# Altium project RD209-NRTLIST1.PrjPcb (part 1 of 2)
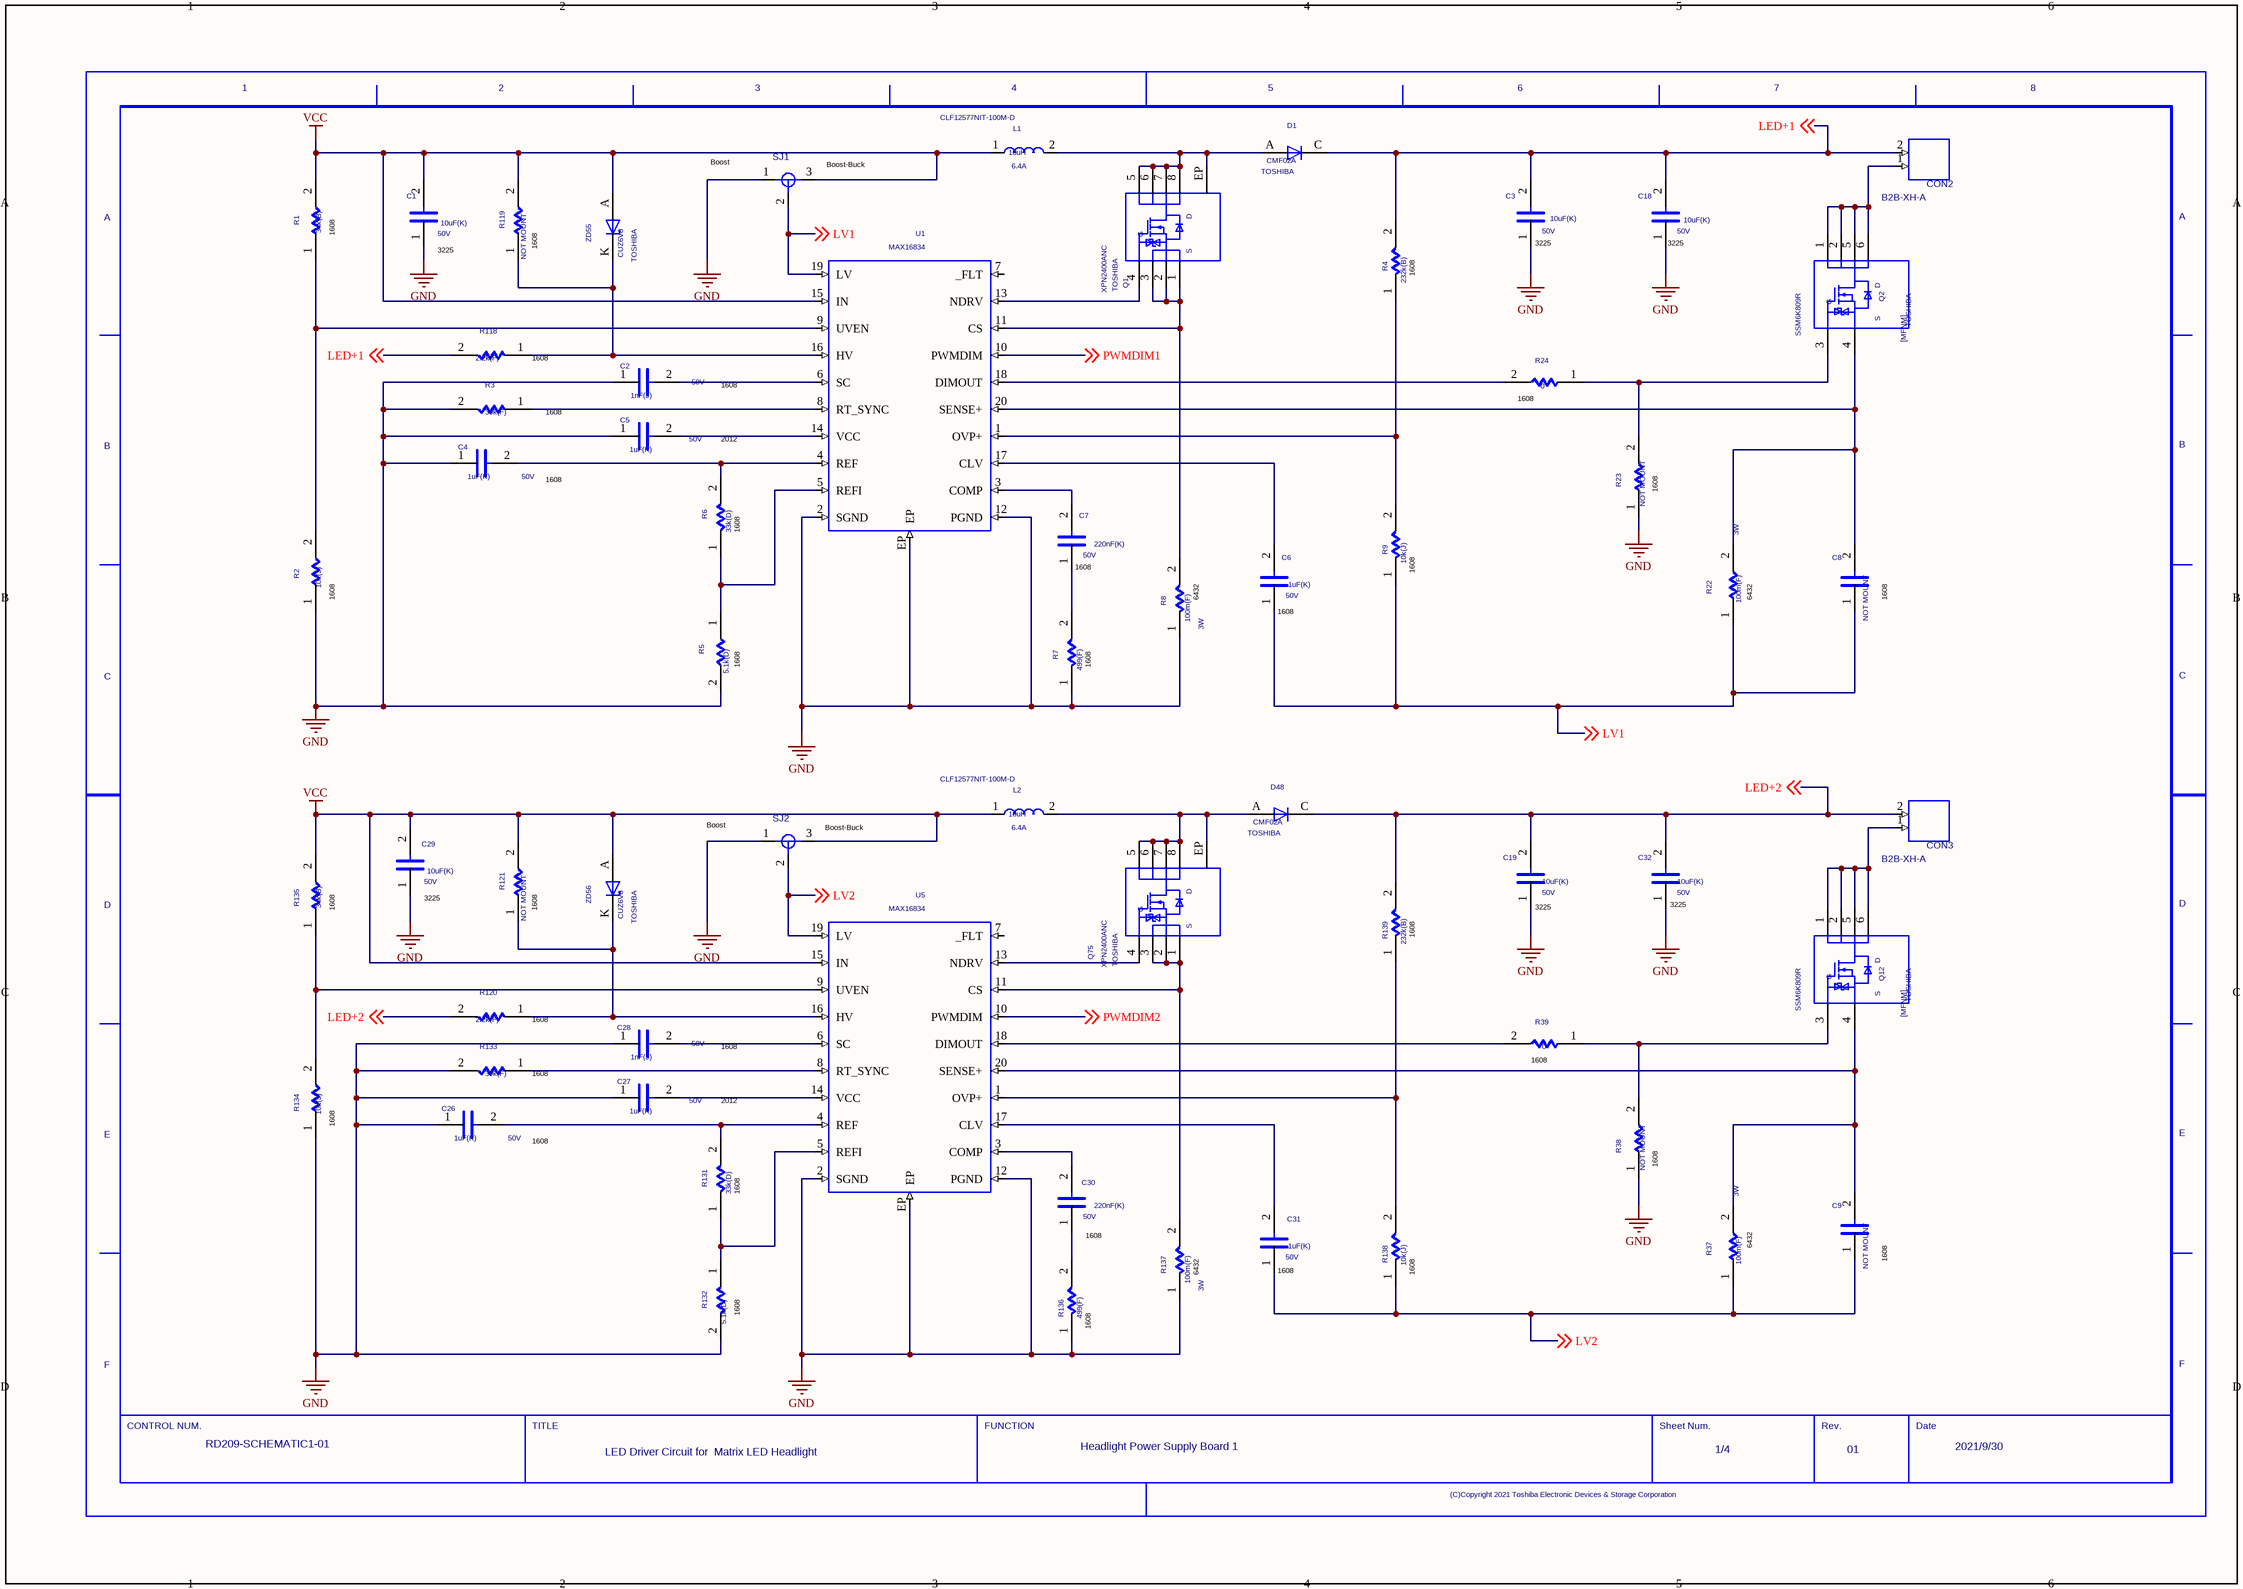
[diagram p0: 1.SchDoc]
4 sheets, 250 parts. Net scope: global (net labels, ports and power ports of the same name join across sheets).
Sheets:
  1.SchDoc
  2.SchDoc
  3.SchDoc
  4.SchDoc

## Sheet 1.SchDoc
size 420 x 297 mm

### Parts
(Parts that share a designator on the sheet are numbered #1, #2 ... from top to bottom, then left to right.)
C1  VAL2: 50V  VAL1: 10uF(K)  (hidden comment: C)
C2  VAL2: 50V  VAL1: 1nF(J)  (hidden comment: C)
C3  VAL2: 50V  VAL1: 10uF(K)  (hidden comment: C)
C4  VAL2: 50V  VAL1: 1uF(K)  (hidden comment: C)
C5  VAL2: 50V  VAL1: 1uF(K)  (hidden comment: C)
C6  VAL2: 50V  VAL1: 1uF(K)  (hidden comment: C)
C7  VAL2: 50V  VAL1: 220nF(K)  (hidden comment: C)
C8  NOTMOUNT: NOT MOUNT  (hidden comment: C)
C9  NOTMOUNT: NOT MOUNT  (hidden comment: C)
C18  VAL2: 50V  VAL1: 10uF(K)  (hidden comment: C)
C19  VAL2: 50V  VAL1: 10uF(K)  (hidden comment: C)
C26  VAL2: 50V  VAL1: 1uF(K)  (hidden comment: C)
C27  VAL2: 50V  VAL1: 1uF(K)  (hidden comment: C)
C28  VAL2: 50V  VAL1: 1nF(J)  (hidden comment: C)
C29  VAL2: 50V  VAL1: 10uF(K)  (hidden comment: C)
C30  VAL2: 50V  VAL1: 220nF(K)  (hidden comment: C)
C31  VAL2: 50V  VAL1: 1uF(K)  (hidden comment: C)
C32  VAL2: 50V  VAL1: 10uF(K)  (hidden comment: C)
CON2  B2B-XH-A  [B2B-XH-A]
CON3  B2B-XH-A  [B2B-XH-A]
D1  USERCOMPTEXT3: TOSHIBA  VAL3: CMF02A  (hidden comment: D)
D48  USERCOMPTEXT3: TOSHIBA  VAL3: CMF02A  (hidden comment: D)
L1  VAL3: CLF12577NIT-100M-D  VAL2: 6.4A  VAL1: 10uH  (hidden comment: L)
L2  VAL3: CLF12577NIT-100M-D  VAL2: 6.4A  VAL1: 10uH  (hidden comment: L)
Q1  USERCOMPTEXT3: TOSHIBA  VAL3: XPN2400ANC  (hidden comment: MFNKR1)
Q2  USERCOMPTEXT3: TOSHIBA  VAL3: SSM6K809R  (hidden comment: MFNM)
Q12  USERCOMPTEXT3: TOSHIBA  VAL3: SSM6K809R  (hidden comment: MFNM)
Q75  USERCOMPTEXT3: TOSHIBA  VAL3: XPN2400ANC  (hidden comment: MFNKR1)
R1  VAL1: 34k(B)  (hidden comment: R)
R2  VAL1: 10k(J)  (hidden comment: R)
R3  VAL1: 39k(F)  (hidden comment: R)
R4  VAL1: 232k(B)  (hidden comment: R)
R5  VAL1: 5.1k(D)  (hidden comment: R)
R6  VAL1: 33k(D)  (hidden comment: R)
R7  VAL1: 499(F)  (hidden comment: R)
R8  VAL2: 3W  VAL1: 100m(F)  (hidden comment: R)
R9  VAL1: 10k(J)  (hidden comment: R)
R22  VAL2: 3W  VAL1: 100m(F)  (hidden comment: R)
R23  NOTMOUNT: NOT MOUNT  (hidden comment: R)
R24  VAL1: 0  (hidden comment: R)
R37  VAL2: 3W  VAL1: 100m(F)  (hidden comment: R)
R38  NOTMOUNT: NOT MOUNT  (hidden comment: R)
R39  VAL1: 0  (hidden comment: R)
R118  VAL1: 2.2k(F)  (hidden comment: R)
R119  NOTMOUNT: NOT MOUNT  (hidden comment: R)
R120  VAL1: 2.2k(F)  (hidden comment: R)
R121  NOTMOUNT: NOT MOUNT  (hidden comment: R)
R131  VAL1: 33k(D)  (hidden comment: R)
R132  VAL1: 5.1k(D)  (hidden comment: R)
R133  VAL1: 39k(F)  (hidden comment: R)
R134  VAL1: 10k(J)  (hidden comment: R)
R135  VAL1: 34k(B)  (hidden comment: R)
R136  VAL1: 499(F)  (hidden comment: R)
R137  VAL2: 3W  VAL1: 100m(F)  (hidden comment: R)
R138  VAL1: 10k(J)  (hidden comment: R)
R139  VAL1: 232k(B)  (hidden comment: R)
SJ1  SJ2W  (value not drawn)
SJ2  SJ2W  (value not drawn)
U1  MAX16834
U5  MAX16834
U?#1  DATE: 2021/9/30  REVISION: 01  SHEETNUMBER: 1/4  FUNCTION: Headlight Power Supply Board 1  TITLE: LED Driver Circuit for / Matrix LED Headlight  DRAWINGNUMBER: RD209-SCHEMATIC1-01  (hidden comment: WAKU_DEF100)
ZD55  USERCOMPTEXT3: TOSHIBA  VAL3: CUZ6V8  (hidden comment: ZD)
ZD56  USERCOMPTEXT3: TOSHIBA  VAL3: CUZ6V8  (hidden comment: ZD)

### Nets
GND: C1.1 C2.1 C3.1 C4.1 C5.1 C18.1 C19.1 C26.1 C27.1 C28.1 C29.1 C32.1 R2.1 R3.2 R5.2 R7.1 R8.1 R23.1 R38.1 R132.2 R133.2 R134.1 R136.1 R137.1 SJ1.1 SJ2.1 U1.2(SGND) U1.12(PGND) U1.EP U5.2(SGND) U5.12(PGND) U5.EP
VCC: C1.2 C29.2 L1.1 L2.1 R1.2 R119.2 R121.2 R135.2 SJ1.3 SJ2.3 U1.15(IN) U5.15(IN) ZD55.A ZD56.A
LED+1: C3.2 C18.2 CON2.2 D1.C R4.2 R118.2 ; off-sheet LED+1
LED+2: C19.2 C32.2 CON3.2 D48.C R120.2 R139.2 ; off-sheet LED+2
LED-1: CON2.1 Q2.1 Q2.2 Q2.5 Q2.6
LV1: C6.1 C8.1 R9.1 R22.1 SJ1.2 U1.19(LV) ; off-sheet LV1
LV2: C9.1 C31.1 R37.1 R138.1 SJ2.2 U5.19(LV) ; off-sheet LV2
N00268: R5.1 R6.1 U1.5(REFI)
N00273: R3.1 U1.8(RT_SYNC)
N00275: R1.1 R2.2 U1.9(UVEN)
N00392: D1.A L1.2 Q1.5 Q1.6 Q1.7 Q1.8 Q1.EP
N00398: C7.2 U1.3(COMP)
N00400: C6.2 U1.17(CLV)
N00402: R4.1 R9.2 U1.1(OVP+)
N00897: C8.2 Q2.4 R22.2 U1.20(SENSE+)
N00907: R24.2 U1.18(DIMOUT)
N00925: R118.1 R119.1 U1.16(HV) ZD55.K(C)
N01084: C4.2 R6.2 U1.4(REF)
PWMDIM1: U1.10(PWMDIM) ; off-sheet PWMDIM1
PWMDIM2: U5.10(PWMDIM) ; off-sheet PWMDIM2
SIG2: Q1.1 Q1.2 Q1.3 R8.2 U1.11(CS)
SIG212: C5.2 U1.14(VCC)
SIG213: C2.2 U1.6(SC)
SIG216: Q1.4 U1.13(NDRV)
SIG218: C7.1 R7.2
SIG223: Q2.3 R23.2 R24.1
SIG224: R133.1 U5.8(RT_SYNC)
SIG225: C28.2 U5.6(SC)
SIG229: C26.2 R131.2 U5.4(REF)
SIG230: C31.2 U5.17(CLV)
SIG231: C27.2 U5.14(VCC)
SIG233: R134.2 R135.1 U5.9(UVEN)
SIG235: C30.2 U5.3(COMP)
SIG236: Q75.1 Q75.2 Q75.3 R137.2 U5.11(CS)
SIG237: R138.2 R139.1 U5.1(OVP+)
SIG238: R120.1 R121.1 U5.16(HV) ZD56.K(C)
SIG243: C30.1 R136.2
SIG244: Q12.3 R38.2 R39.1
SIG245: R131.1 R132.1 U5.5(REFI)
SIG250: D48.A L2.2 Q75.5 Q75.6 Q75.7 Q75.8 Q75.EP
SIG251: Q75.4 U5.13(NDRV)
SIG662: R39.2 U5.18(DIMOUT)
SIG663: CON3.1 Q12.1 Q12.2 Q12.5 Q12.6
SIG664: C9.2 Q12.4 R37.2 U5.20(SENSE+)

Not connected (* = marked no-connect by the designer): U1 7(_FLT); U5 7(_FLT)

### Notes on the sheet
- (near SJ1) Boost
- (near SJ1) Boost-Buck
- (near R1) 1608
- (near C1) 3225
- (near R119) 1608
- (near C3) 3225
- (near C18) 3225
- (near R4) 1608
- (near R118) 1608
- 1608
- (near R3) 1608
- 2012
- (near R24) 1608
- (near R6) 1608
- (near R23) 1608
- (near R2) 1608
- (near C7) 1608
- (near R8) 6432
- (near R9) 1608
- (near R22) 6432
- (near C8) 1608
- (near R5) 1608
- (near R7) 1608
- (near C6) 1608
- (near SJ2) Boost
- (near SJ2) Boost-Buck
- (near R135) 1608
- (near C29) 3225
- (near R121) 1608
- (near R139) 1608
- (near C19) 3225
- (near C32) 3225
- (near R120) 1608
- (near R39) 1608
- (near R134) 1608
- (near R133) 1608
- (near R131) 1608
- (near R38) 1608
- (near R137) 6432
- (near C31) 1608
- (near R138) 1608
- (near R37) 6432
- (near C9) 1608
- (near R132) 1608
- (near R136) 1608

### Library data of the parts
C1 = C: TIME: 17:22:43; UPDATEUSER: t5459927; SAVECOUNT: 1; OriginalSymbolOrigin: (2540,7620); INSTANCENAME: cmp468; CDBNAME: C1210K
C2 = C: TIME: 17:22:43; UPDATEUSER: t5459927; SAVECOUNT: 1; OriginalSymbolOrigin: (2540,7620); INSTANCENAME: cmp462; CDBNAME: C0603K_1
C3 = C: TIME: 17:22:43; UPDATEUSER: t5459927; SAVECOUNT: 1; OriginalSymbolOrigin: (2540,7620); INSTANCENAME: cmp474; CDBNAME: C1210K
C4 = C: TIME: 17:22:43; UPDATEUSER: t5459927; SAVECOUNT: 1; OriginalSymbolOrigin: (2540,7620); INSTANCENAME: cmp457; CDBNAME: C0603K_3
C5 = C: TIME: 17:22:43; UPDATEUSER: t5459927; SAVECOUNT: 1; OriginalSymbolOrigin: (2540,7620); INSTANCENAME: cmp459; CDBNAME: C0805K_1
C6 = C: TIME: 17:22:43; UPDATEUSER: t5459927; SAVECOUNT: 1; OriginalSymbolOrigin: (2540,7620); INSTANCENAME: cmp481; CDBNAME: C0603K_3
C7 = C: TIME: 17:22:43; UPDATEUSER: t5459927; SAVECOUNT: 1; OriginalSymbolOrigin: (2540,7620); INSTANCENAME: cmp482; CDBNAME: C0603K_4
C8 = C: TIME: 17:22:43; UPDATEUSER: t5459927; SAVECOUNT: 1; OriginalSymbolOrigin: (2540,7620); INSTANCENAME: cmp493; CDBNAME: C0603K
C9 = C: TIME: 17:22:43; UPDATEUSER: t5459927; SAVECOUNT: 1; OriginalSymbolOrigin: (2540,7620); INSTANCENAME: cmp590; CDBNAME: C0603K
C18 = C: TIME: 17:22:43; UPDATEUSER: t5459927; SAVECOUNT: 1; OriginalSymbolOrigin: (2540,7620); INSTANCENAME: cmp472; CDBNAME: C1210K
C19 = C: TIME: 17:22:43; UPDATEUSER: t5459927; SAVECOUNT: 1; OriginalSymbolOrigin: (2540,7620); INSTANCENAME: cmp593; CDBNAME: C1210K
C26 = C: TIME: 17:22:43; UPDATEUSER: t5459927; SAVECOUNT: 1; OriginalSymbolOrigin: (2540,7620); INSTANCENAME: cmp560; CDBNAME: C0603K_3
C27 = C: TIME: 17:22:43; UPDATEUSER: t5459927; SAVECOUNT: 1; OriginalSymbolOrigin: (2540,7620); INSTANCENAME: cmp586; CDBNAME: C0805K_1
C28 = C: TIME: 17:22:43; UPDATEUSER: t5459927; SAVECOUNT: 1; OriginalSymbolOrigin: (2540,7620); INSTANCENAME: cmp596; CDBNAME: C0603K_1
C29 = C: TIME: 17:22:43; UPDATEUSER: t5459927; SAVECOUNT: 1; OriginalSymbolOrigin: (2540,7620); INSTANCENAME: cmp558; CDBNAME: C1210K
C30 = C: TIME: 17:22:43; UPDATEUSER: t5459927; SAVECOUNT: 1; OriginalSymbolOrigin: (2540,7620); INSTANCENAME: cmp562; CDBNAME: C0603K_4
C31 = C: TIME: 17:22:43; UPDATEUSER: t5459927; SAVECOUNT: 1; OriginalSymbolOrigin: (2540,7620); INSTANCENAME: cmp584; CDBNAME: C0603K_3
C32 = C: TIME: 17:22:43; UPDATEUSER: t5459927; SAVECOUNT: 1; OriginalSymbolOrigin: (2540,7620); INSTANCENAME: cmp554; CDBNAME: C1210K
CON2 CON3 = B2B_XH_A: SAVECOUNT: 1; COMP: B2_BX_HA; UPDATEUSER: t5459927; UPDATETIME: 17:22:42; OriginalSymbolOrigin: (0,0); COMPONENTNAME: CON; INSTANCENAME: INS9160
D1 D48 = D: SAVEAREA0: -225,-91,12804,7836; SAVECOUNT: 3; TIME: 14:49:55; UPDATEUSER: 19870035; UPDATETIME: 14:20:16; OriginalSymbolOrigin: (5080,5080); CDBNAME: M-FLAT
L1 = L: COMP: CLF12577NI_D; TIME: 17:22:43; UPDATEUSER: t5459927; SAVECOUNT: 1; OriginalSymbolOrigin: (2540,5080); INSTANCENAME: cmp470; CDBNAME: CLF12577NI-D
L2 = L: COMP: CLF12577NI_D; TIME: 17:22:43; UPDATEUSER: t5459927; SAVECOUNT: 1; OriginalSymbolOrigin: (2540,5080); INSTANCENAME: cmp575; CDBNAME: CLF12577NI-D
Q1 Q75 = MFNKR1: TIME: 17:22:43; SAVECOUNT: 2; SAVEAREA0: -5755,-491,27794,24105; COMP: TSON_ADVANCE_WF_1; UPDATETIME: 09:26:31; UPDATEUSER: t5459927; OriginalSymbolOrigin: (5080,20320); COMPONENTNAME: Q
Q2 = MFNM: TIME: 17:22:43; SAVECOUNT: 1; SAVEAREA0: -6986,-322,29385,23602; UPDATEUSER: t5459927; OriginalSymbolOrigin: (5080,20320); COMPONENTNAME: Q; INSTANCENAME: cmp496; CDBNAME: TSOP6F
Q12 = MFNM: TIME: 17:22:43; SAVECOUNT: 1; SAVEAREA0: -6986,-322,29385,23602; UPDATEUSER: t5459927; OriginalSymbolOrigin: (5080,20320); COMPONENTNAME: Q; INSTANCENAME: cmp553; CDBNAME: TSOP6F
R1 = R: TIME: 17:22:43; UPDATEUSER: t5459927; SAVECOUNT: 1; OriginalSymbolOrigin: (5080,5080); VAL2: 100mW; INSTANCENAME: cmp447; CDBNAME: R0603_1
R2 = R: TIME: 17:22:43; UPDATEUSER: t5459927; SAVECOUNT: 1; OriginalSymbolOrigin: (5080,5080); VAL2: 100mW; INSTANCENAME: cmp448; CDBNAME: R0603_6
R3 = R: TIME: 17:22:43; UPDATEUSER: t5459927; SAVECOUNT: 1; OriginalSymbolOrigin: (5080,5080); VAL2: 100mW; INSTANCENAME: cmp460; CDBNAME: R0603_8
R4 = R: TIME: 17:22:43; UPDATEUSER: t5459927; SAVECOUNT: 1; OriginalSymbolOrigin: (5080,5080); VAL2: 63mW; INSTANCENAME: cmp478; CDBNAME: R0603_9
R5 = R: TIME: 17:22:43; UPDATEUSER: t5459927; SAVECOUNT: 1; OriginalSymbolOrigin: (5080,5080); VAL2: 100mW; INSTANCENAME: cmp450; CDBNAME: R0603_10
R6 = R#1: TIME: 17:22:43; UPDATEUSER: t5459927; SAVECOUNT: 1; OriginalSymbolOrigin: (5080,5080); CaptureCellPackProp: R##1; VAL2: 100mW; INSTANCENAME: cmp606; CDBNAME: R0603_11
R7 = R: TIME: 17:22:43; UPDATEUSER: t5459927; SAVECOUNT: 1; OriginalSymbolOrigin: (5080,5080); VAL2: 125mW; INSTANCENAME: cmp483; CDBNAME: R0603_12
R8 = R: TIME: 17:22:43; UPDATEUSER: t5459927; SAVECOUNT: 1; OriginalSymbolOrigin: (5080,5080); INSTANCENAME: cmp484; CDBNAME: R2512
R9 = R: TIME: 17:22:43; UPDATEUSER: t5459927; SAVECOUNT: 1; OriginalSymbolOrigin: (5080,5080); VAL2: 100mW; INSTANCENAME: cmp479; CDBNAME: R0603_6
R22 = R: TIME: 17:22:43; UPDATEUSER: t5459927; SAVECOUNT: 1; OriginalSymbolOrigin: (5080,5080); INSTANCENAME: cmp492; CDBNAME: R2512
R23 = R: TIME: 17:22:43; UPDATEUSER: t5459927; SAVECOUNT: 1; OriginalSymbolOrigin: (5080,5080); INSTANCENAME: cmp489; CDBNAME: R0603
R24 = R: TIME: 17:22:43; UPDATEUSER: t5459927; SAVECOUNT: 1; OriginalSymbolOrigin: (5080,5080); INSTANCENAME: cmp498; CDBNAME: R0603_7
R37 = R: TIME: 17:22:43; UPDATEUSER: t5459927; SAVECOUNT: 1; OriginalSymbolOrigin: (5080,5080); INSTANCENAME: cmp559; CDBNAME: R2512
R38 = R: TIME: 17:22:43; UPDATEUSER: t5459927; SAVECOUNT: 1; OriginalSymbolOrigin: (5080,5080); INSTANCENAME: cmp592; CDBNAME: R0603
R39 = R: TIME: 17:22:43; UPDATEUSER: t5459927; SAVECOUNT: 1; OriginalSymbolOrigin: (5080,5080); INSTANCENAME: cmp550; CDBNAME: R0603_7
R118 = R: TIME: 17:22:43; UPDATEUSER: t5459927; SAVECOUNT: 1; OriginalSymbolOrigin: (5080,5080); VAL2: 100mW; INSTANCENAME: cmp466; CDBNAME: R0603_2
R119 = R: TIME: 17:22:43; UPDATEUSER: t5459927; SAVECOUNT: 1; OriginalSymbolOrigin: (5080,5080); INSTANCENAME: cmp469; CDBNAME: R0603
R120 = R: TIME: 17:22:43; UPDATEUSER: t5459927; SAVECOUNT: 1; OriginalSymbolOrigin: (5080,5080); VAL2: 100mW; INSTANCENAME: cmp591; CDBNAME: R0603_2
R121 = R: TIME: 17:22:43; UPDATEUSER: t5459927; SAVECOUNT: 1; OriginalSymbolOrigin: (5080,5080); INSTANCENAME: cmp582; CDBNAME: R0603
R131 = R#1: TIME: 17:22:43; UPDATEUSER: t5459927; SAVECOUNT: 1; OriginalSymbolOrigin: (5080,5080); CaptureCellPackProp: R##1; VAL2: 100mW; INSTANCENAME: cmp607; CDBNAME: R0603_11
R132 = R: TIME: 17:22:43; UPDATEUSER: t5459927; SAVECOUNT: 1; OriginalSymbolOrigin: (5080,5080); VAL2: 100mW; INSTANCENAME: cmp551; CDBNAME: R0603_10
R133 = R: TIME: 17:22:43; UPDATEUSER: t5459927; SAVECOUNT: 1; OriginalSymbolOrigin: (5080,5080); VAL2: 100mW; INSTANCENAME: cmp579; CDBNAME: R0603_8
R134 = R: TIME: 17:22:43; UPDATEUSER: t5459927; SAVECOUNT: 1; OriginalSymbolOrigin: (5080,5080); VAL2: 100mW; INSTANCENAME: cmp595; CDBNAME: R0603_6
R135 = R: TIME: 17:22:43; UPDATEUSER: t5459927; SAVECOUNT: 1; OriginalSymbolOrigin: (5080,5080); VAL2: 100mW; INSTANCENAME: cmp561; CDBNAME: R0603_1
R136 = R: TIME: 17:22:43; UPDATEUSER: t5459927; SAVECOUNT: 1; OriginalSymbolOrigin: (5080,5080); VAL2: 125mW; INSTANCENAME: cmp555; CDBNAME: R0603_12
R137 = R: TIME: 17:22:43; UPDATEUSER: t5459927; SAVECOUNT: 1; OriginalSymbolOrigin: (5080,5080); INSTANCENAME: cmp571; CDBNAME: R2512
R138 = R: TIME: 17:22:43; UPDATEUSER: t5459927; SAVECOUNT: 1; OriginalSymbolOrigin: (5080,5080); VAL2: 100mW; INSTANCENAME: cmp564; CDBNAME: R0603_6
R139 = R: TIME: 17:22:43; UPDATEUSER: t5459927; SAVECOUNT: 1; OriginalSymbolOrigin: (5080,5080); VAL2: 63mW; INSTANCENAME: cmp581; CDBNAME: R0603_9
SJ1 = SJ2W: SAVECOUNT: 1; COMP: SJ_2; SAVEAREA0: -15743,-4510,23437,11881; UPDATEUSER: t5459927; UPDATETIME: 17:22:42; OriginalSymbolOrigin: (2540,7620); COMPONENTNAME: SJ; INSTANCENAME: cmp600
SJ2 = SJ2W: SAVECOUNT: 1; COMP: SJ_2; SAVEAREA0: -15743,-4510,23437,11881; UPDATEUSER: t5459927; UPDATETIME: 17:22:42; OriginalSymbolOrigin: (2540,7620); COMPONENTNAME: SJ; INSTANCENAME: cmp604
U1 U5 = MAX16834: SAVECOUNT: 1; COMP: 20-TQFN; SAVEAREA0: -47937,-54417,76568,2975; UPDATEUSER: t5459927; UPDATETIME: 17:22:42; OriginalSymbolOrigin: (0,0); COMPONENTNAME: IC; INSTANCENAME: cmp580
U?#1 = WAKU_DEF100: PLOTTIME: HH:MM; SAVEAREA0: 147884,-66467,487065,89883; TIME: 14:30:25; UPDATEUSER: t5459927; UPDATETIME: 12:50:54; SAVECOUNT: 7; OriginalSymbolOrigin: (10160,284480)
ZD55 = ZD: TIME: 17:22:43; SAVECOUNT: 1; SAVEAREA0: -4630,-153,17114,13055; UPDATEUSER: t5459927; OriginalSymbolOrigin: (5080,5080); INSTANCENAME: cmp445; CDBNAME: USC
ZD56 = ZD: TIME: 17:22:43; SAVECOUNT: 1; SAVEAREA0: -4630,-153,17114,13055; UPDATEUSER: t5459927; OriginalSymbolOrigin: (5080,5080); INSTANCENAME: cmp588; CDBNAME: USC

## Sheet 2.SchDoc
size 420 x 297 mm
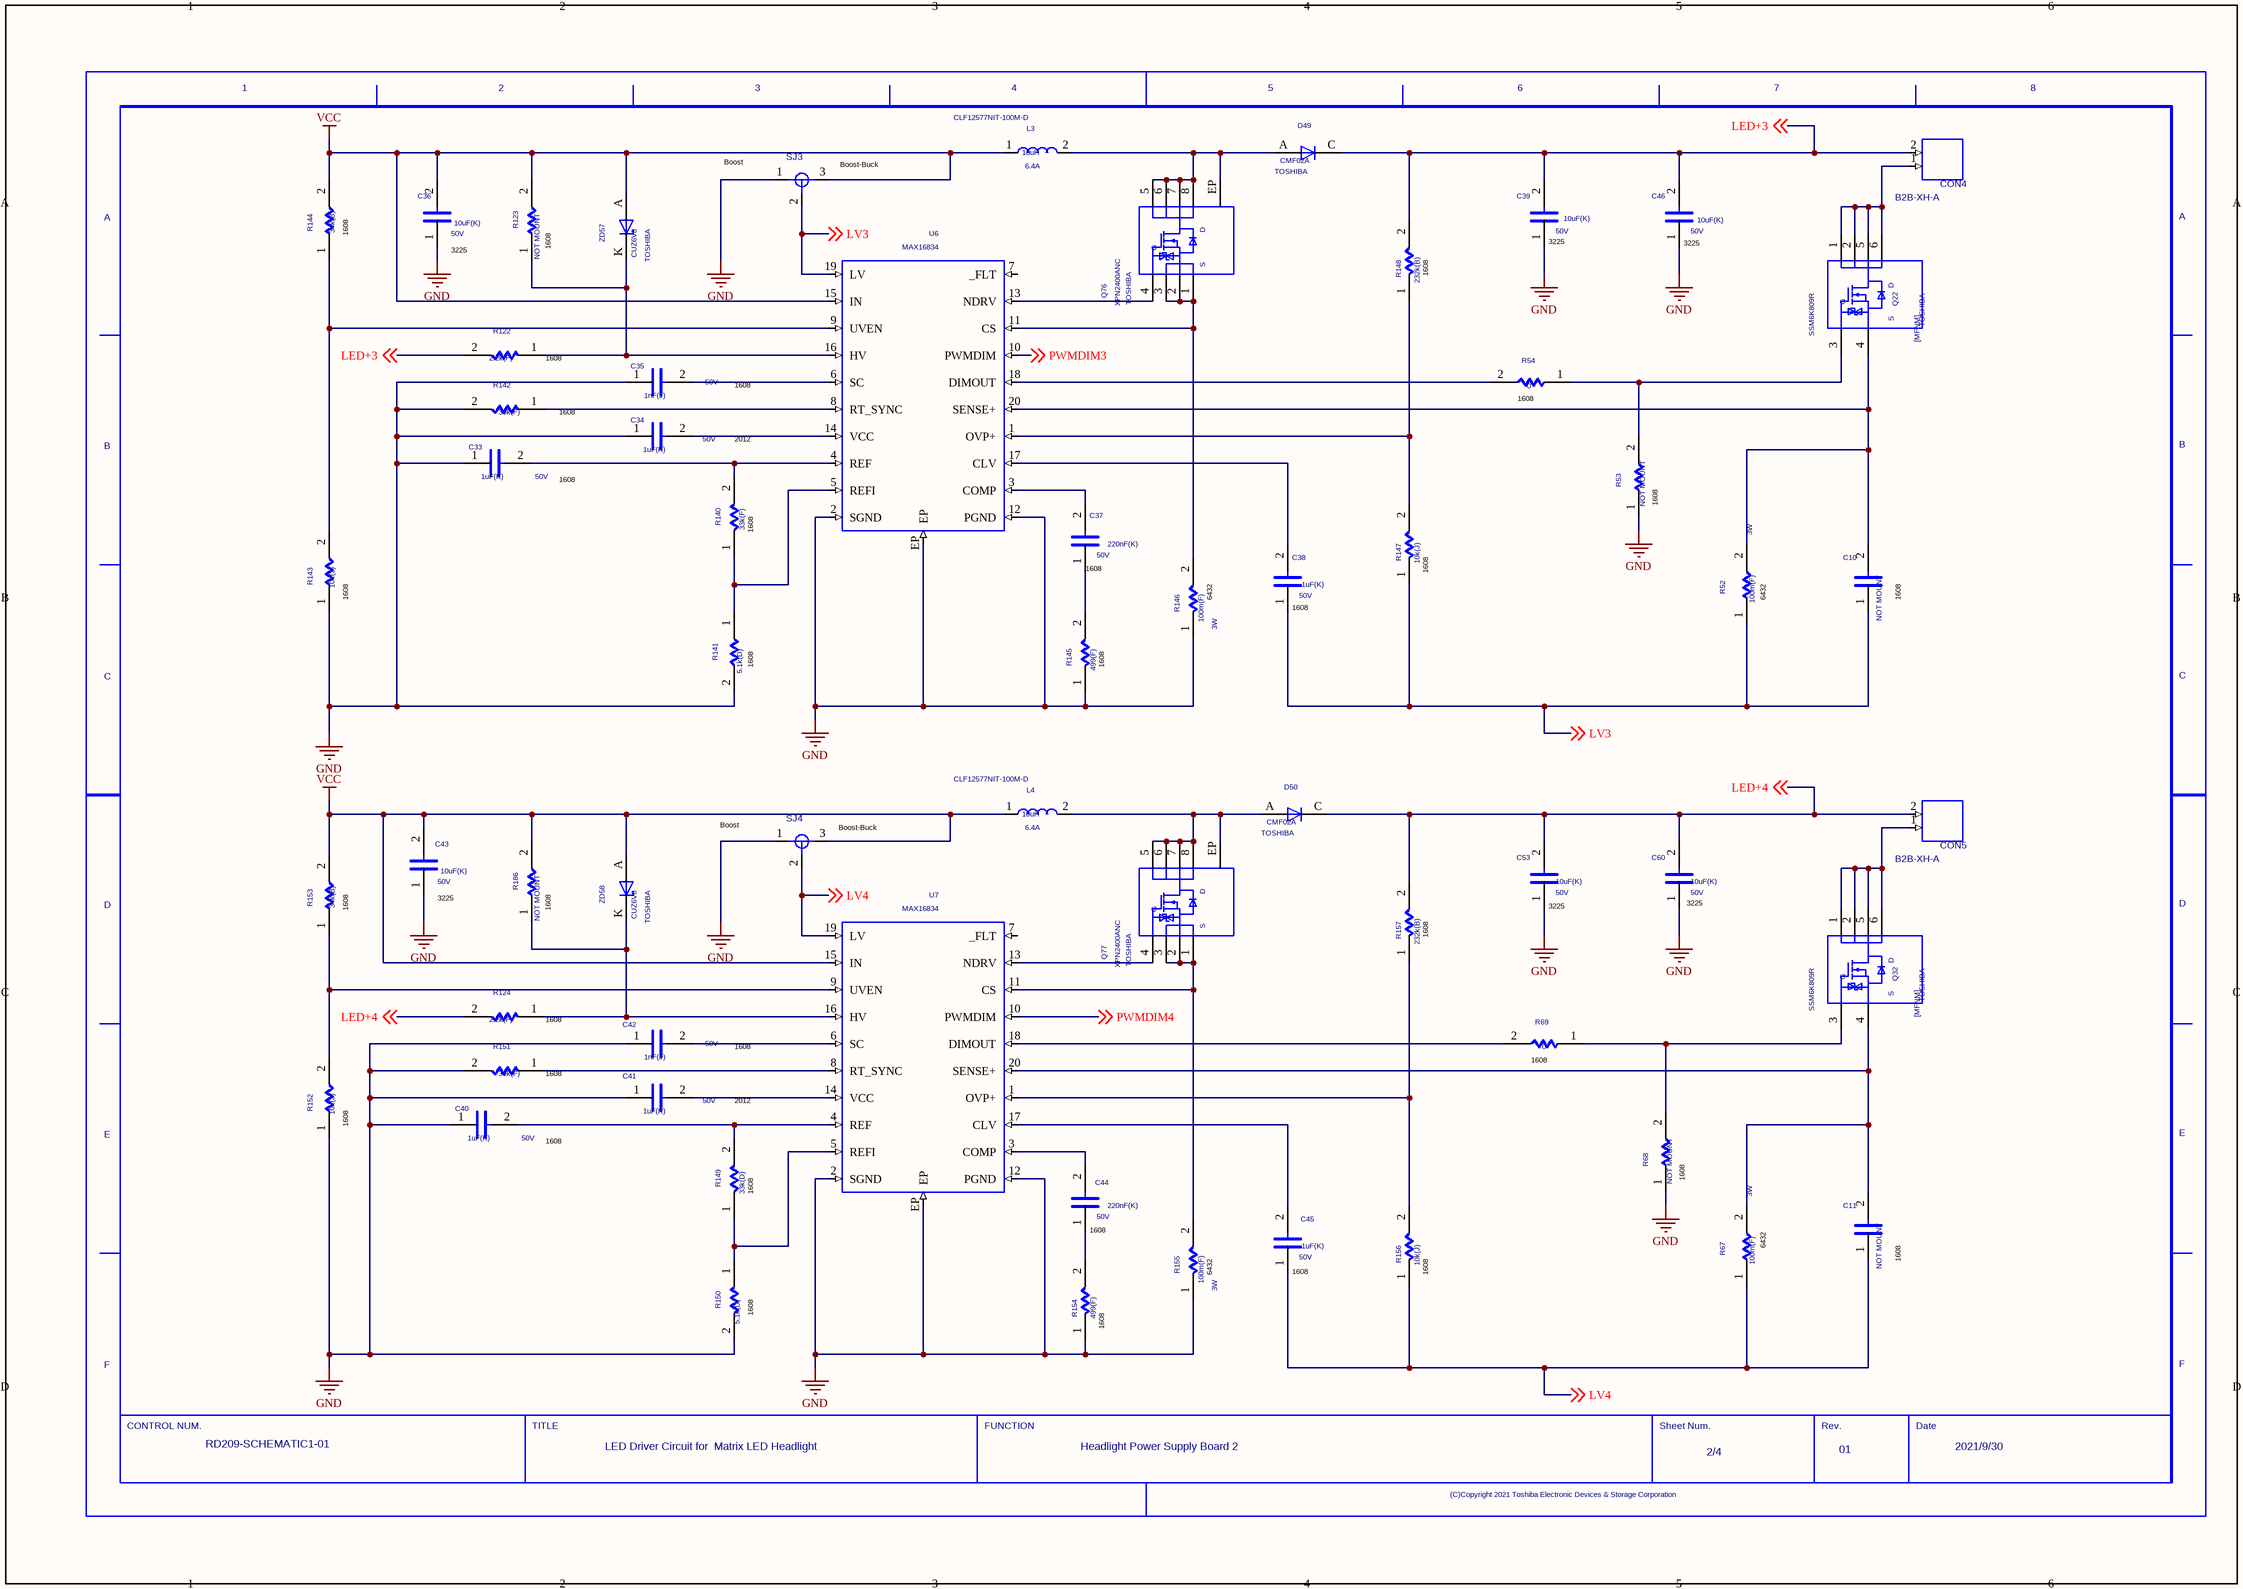
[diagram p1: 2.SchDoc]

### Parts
(Parts that share a designator on the sheet are numbered #1, #2 ... from top to bottom, then left to right.)
C10  NOTMOUNT: NOT MOUNT  (hidden comment: C)
C11  NOTMOUNT: NOT MOUNT  (hidden comment: C)
C33  VAL2: 50V  VAL1: 1uF(K)  (hidden comment: C)
C34  VAL2: 50V  VAL1: 1uF(K)  (hidden comment: C)
C35  VAL2: 50V  VAL1: 1nF(J)  (hidden comment: C)
C36  VAL2: 50V  VAL1: 10uF(K)  (hidden comment: C)
C37  VAL2: 50V  VAL1: 220nF(K)  (hidden comment: C)
C38  VAL2: 50V  VAL1: 1uF(K)  (hidden comment: C)
C39  VAL2: 50V  VAL1: 10uF(K)  (hidden comment: C)
C40  VAL2: 50V  VAL1: 1uF(K)  (hidden comment: C)
C41  VAL2: 50V  VAL1: 1uF(K)  (hidden comment: C)
C42  VAL2: 50V  VAL1: 1nF(J)  (hidden comment: C)
C43  VAL2: 50V  VAL1: 10uF(K)  (hidden comment: C)
C44  VAL2: 50V  VAL1: 220nF(K)  (hidden comment: C)
C45  VAL2: 50V  VAL1: 1uF(K)  (hidden comment: C)
C46  VAL2: 50V  VAL1: 10uF(K)  (hidden comment: C)
C53  VAL2: 50V  VAL1: 10uF(K)  (hidden comment: C)
C60  VAL2: 50V  VAL1: 10uF(K)  (hidden comment: C)
CON4  B2B-XH-A  [B2B-XH-A]
CON5  B2B-XH-A  [B2B-XH-A]
D49  USERCOMPTEXT3: TOSHIBA  VAL3: CMF02A  (hidden comment: D)
D50  USERCOMPTEXT3: TOSHIBA  VAL3: CMF02A  (hidden comment: D)
L3  VAL3: CLF12577NIT-100M-D  VAL2: 6.4A  VAL1: 10uH  (hidden comment: L)
L4  VAL3: CLF12577NIT-100M-D  VAL2: 6.4A  VAL1: 10uH  (hidden comment: L)
Q22  USERCOMPTEXT3: TOSHIBA  VAL3: SSM6K809R  (hidden comment: MFNM)
Q32  USERCOMPTEXT3: TOSHIBA  VAL3: SSM6K809R  (hidden comment: MFNM)
Q76  USERCOMPTEXT3: TOSHIBA  VAL3: XPN2400ANC  (hidden comment: MFNKR1)
Q77  USERCOMPTEXT3: TOSHIBA  VAL3: XPN2400ANC  (hidden comment: MFNKR1)
R52  VAL2: 3W  VAL1: 100m(F)  (hidden comment: R)
R53  NOTMOUNT: NOT MOUNT  (hidden comment: R)
R54  VAL1: 0  (hidden comment: R)
R67  VAL2: 3W  VAL1: 100m(F)  (hidden comment: R)
R68  NOTMOUNT: NOT MOUNT  (hidden comment: R)
R69  VAL1: 0  (hidden comment: R)
R122  VAL1: 2.2k(F)  (hidden comment: R)
R123  NOTMOUNT: NOT MOUNT  (hidden comment: R)
R124  VAL1: 2.2k(F)  (hidden comment: R)
R140  VAL1: 33k(F)  (hidden comment: R)
R141  VAL1: 5.1k(D)  (hidden comment: R)
R142  VAL1: 39k(F)  (hidden comment: R)
R143  VAL1: 10k(J)  (hidden comment: R)
R144  VAL1: 34k(B)  (hidden comment: R)
R145  VAL1: 499(F)  (hidden comment: R)
R146  VAL2: 3W  VAL1: 100m(F)  (hidden comment: R)
R147  VAL1: 10k(J)  (hidden comment: R)
R148  VAL1: 232k(B)  (hidden comment: R)
R149  VAL1: 33k(D)  (hidden comment: R)
R150  VAL1: 5.1k(D)  (hidden comment: R)
R151  VAL1: 39k(F)  (hidden comment: R)
R152  VAL1: 10k(J)  (hidden comment: R)
R153  VAL1: 34k(B)  (hidden comment: R)
R154  VAL1: 499(F)  (hidden comment: R)
R155  VAL2: 3W  VAL1: 100m(F)  (hidden comment: R)
R156  VAL1: 10k(J)  (hidden comment: R)
R157  VAL1: 232k(B)  (hidden comment: R)
R186  NOTMOUNT: NOT MOUNT  (hidden comment: R)
SJ3  SJ2W  (value not drawn)
SJ4  SJ2W  (value not drawn)
U6  MAX16834
U7  MAX16834
U?#2  DATE: 2021/9/30  REVISION: 01  FUNCTION: Headlight Power Supply Board 2  SHEETNUMBER: 2/4  TITLE: LED Driver Circuit for / Matrix LED Headlight  DRAWINGNUMBER: RD209-SCHEMATIC1-01  (hidden comment: WAKU_DEF100)
ZD57  USERCOMPTEXT3: TOSHIBA  VAL3: CUZ6V8  (hidden comment: ZD)
ZD58  USERCOMPTEXT3: TOSHIBA  VAL3: CUZ6V8  (hidden comment: ZD)

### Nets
GND: C33.1 C34.1 C35.1 C36.1 C39.1 C40.1 C41.1 C42.1 C43.1 C46.1 C53.1 C60.1 R53.1 R68.1 R141.2 R142.2 R143.1 R145.1 R146.1 R150.2 R151.2 R152.1 R154.1 R155.1 SJ3.1 SJ4.1 U6.2(SGND) U6.12(PGND) U6.EP U7.2(SGND) U7.12(PGND) U7.EP
VCC: C36.2 C43.2 L3.1 L4.1 R123.2 R144.2 R153.2 R186.2 SJ3.3 SJ4.3 U6.15(IN) U7.15(IN) ZD57.A ZD58.A
LED+3: C39.2 C46.2 CON4.2 D49.C R122.2 R148.2 ; off-sheet LED+3
LED+4: C53.2 C60.2 CON5.2 D50.C R124.2 R157.2 ; off-sheet LED+4
LV3: C10.1 C38.1 R52.1 R147.1 SJ3.2 U6.19(LV) ; off-sheet LV3
LV4: C11.1 C45.1 R67.1 R156.1 SJ4.2 U7.19(LV) ; off-sheet LV4
PWMDIM3: U6.10(PWMDIM) ; off-sheet PWMDIM3
PWMDIM4: U7.10(PWMDIM) ; off-sheet PWMDIM4
SIG668: R142.1 U6.8(RT_SYNC)
SIG669: Q77.1 Q77.2 Q77.3 R155.2 U7.11(CS)
SIG670: D50.A L4.2 Q77.5 Q77.6 Q77.7 Q77.8 Q77.EP
SIG671: CON5.1 Q32.1 Q32.2 Q32.5 Q32.6
SIG673: C44.2 U7.3(COMP)
SIG674: C45.2 U7.17(CLV)
SIG675: R156.2 R157.1 U7.1(OVP+)
SIG676: R69.2 U7.18(DIMOUT)
SIG677: R147.2 R148.1 U6.1(OVP+)
SIG679: R143.2 R144.1 U6.9(UVEN)
SIG680: R151.1 U7.8(RT_SYNC)
SIG681: C42.2 U7.6(SC)
SIG682: Q32.3 R68.2 R69.1
SIG683: R54.2 U6.18(DIMOUT)
SIG686: R124.1 R186.1 U7.16(HV) ZD58.K(C)
SIG690: R149.1 R150.1 U7.5(REFI)
SIG691: R152.2 R153.1 U7.9(UVEN)
SIG693: C40.2 R149.2 U7.4(REF)
SIG694: Q77.4 U7.13(NDRV)
SIG695: C41.2 U7.14(VCC)
SIG696: C10.2 Q22.4 R52.2 U6.20(SENSE+)
SIG697: D49.A L3.2 Q76.5 Q76.6 Q76.7 Q76.8 Q76.EP
SIG698: R122.1 R123.1 U6.16(HV) ZD57.K(C)
SIG699: Q76.1 Q76.2 Q76.3 R146.2 U6.11(CS)
SIG700: C37.1 R145.2
SIG702: C44.1 R154.2
SIG704: Q22.3 R53.2 R54.1
SIG705: CON4.1 Q22.1 Q22.2 Q22.5 Q22.6
SIG707: R140.1 R141.1 U6.5(REFI)
SIG709: C11.2 Q32.4 R67.2 U7.20(SENSE+)
SIG710: C37.2 U6.3(COMP)
SIG711: C35.2 U6.6(SC)
SIG712: C33.2 R140.2 U6.4(REF)
SIG713: C38.2 U6.17(CLV)
SIG715: C34.2 U6.14(VCC)
SIG717: Q76.4 U6.13(NDRV)

Not connected (* = marked no-connect by the designer): U6 7(_FLT); U7 7(_FLT)

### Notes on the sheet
- (near SJ3) Boost
- (near SJ3) Boost-Buck
- (near R144) 1608
- (near C36) 3225
- (near R123) 1608
- (near C39) 3225
- (near C46) 3225
- (near R148) 1608
- (near R122) 1608
- 1608
- (near R142) 1608
- 2012
- (near R54) 1608
- (near R140) 1608
- (near R53) 1608
- (near R143) 1608
- (near C37) 1608
- (near R146) 6432
- (near R147) 1608
- (near R52) 6432
- (near C10) 1608
- (near R141) 1608
- (near R145) 1608
- (near C38) 1608
- (near SJ4) Boost
- (near SJ4) Boost-Buck
- (near R153) 1608
- (near C43) 3225
- (near R186) 1608
- (near R157) 1608
- (near C53) 3225
- (near C60) 3225
- (near R124) 1608
- (near R69) 1608
- (near R152) 1608
- (near R151) 1608
- (near R149) 1608
- (near R68) 1608
- (near C44) 1608
- (near R155) 6432
- (near C45) 1608
- (near R156) 1608
- (near R67) 6432
- (near C11) 1608
- (near R150) 1608
- (near R154) 1608

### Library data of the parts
C10 = C: TIME: 17:22:43; UPDATEUSER: t5459927; SAVECOUNT: 1; OriginalSymbolOrigin: (2540,7620); INSTANCENAME: cmp621; CDBNAME: C0603K
C11 = C: TIME: 17:22:43; UPDATEUSER: t5459927; SAVECOUNT: 1; OriginalSymbolOrigin: (2540,7620); INSTANCENAME: cmp618; CDBNAME: C0603K
C33 = C: TIME: 17:22:43; UPDATEUSER: t5459927; SAVECOUNT: 1; OriginalSymbolOrigin: (2540,7620); INSTANCENAME: cmp640; CDBNAME: C0603K_3
C34 = C: TIME: 17:22:43; UPDATEUSER: t5459927; SAVECOUNT: 1; OriginalSymbolOrigin: (2540,7620); INSTANCENAME: cmp563; CDBNAME: C0805K_1
C35 = C: TIME: 17:22:43; UPDATEUSER: t5459927; SAVECOUNT: 1; OriginalSymbolOrigin: (2540,7620); INSTANCENAME: cmp588; CDBNAME: C0603K_1
C36 = C: TIME: 17:22:43; UPDATEUSER: t5459927; SAVECOUNT: 1; OriginalSymbolOrigin: (2540,7620); INSTANCENAME: cmp623; CDBNAME: C1210K
C37 = C: TIME: 17:22:43; UPDATEUSER: t5459927; SAVECOUNT: 1; OriginalSymbolOrigin: (2540,7620); INSTANCENAME: cmp596; CDBNAME: C0603K_4
C38 = C: TIME: 17:22:43; UPDATEUSER: t5459927; SAVECOUNT: 1; OriginalSymbolOrigin: (2540,7620); INSTANCENAME: cmp624; CDBNAME: C0603K_3
C39 = C: TIME: 17:22:43; UPDATEUSER: t5459927; SAVECOUNT: 1; OriginalSymbolOrigin: (2540,7620); INSTANCENAME: cmp589; CDBNAME: C1210K
C40 = C: TIME: 17:22:43; UPDATEUSER: t5459927; SAVECOUNT: 1; OriginalSymbolOrigin: (2540,7620); INSTANCENAME: cmp634; CDBNAME: C0603K_3
C41 = C: TIME: 17:22:43; UPDATEUSER: t5459927; SAVECOUNT: 1; OriginalSymbolOrigin: (2540,7620); INSTANCENAME: cmp629; CDBNAME: C0805K_1
C42 = C: TIME: 17:22:43; UPDATEUSER: t5459927; SAVECOUNT: 1; OriginalSymbolOrigin: (2540,7620); INSTANCENAME: cmp601; CDBNAME: C0603K_1
C43 = C: TIME: 17:22:43; UPDATEUSER: t5459927; SAVECOUNT: 1; OriginalSymbolOrigin: (2540,7620); INSTANCENAME: cmp574; CDBNAME: C1210K
C44 = C: TIME: 17:22:43; UPDATEUSER: t5459927; SAVECOUNT: 1; OriginalSymbolOrigin: (2540,7620); INSTANCENAME: cmp606; CDBNAME: C0603K_4
C45 = C: TIME: 17:22:43; UPDATEUSER: t5459927; SAVECOUNT: 1; OriginalSymbolOrigin: (2540,7620); INSTANCENAME: cmp592; CDBNAME: C0603K_3
C46 = C: TIME: 17:22:43; UPDATEUSER: t5459927; SAVECOUNT: 1; OriginalSymbolOrigin: (2540,7620); INSTANCENAME: cmp643; CDBNAME: C1210K
C53 = C: TIME: 17:22:43; UPDATEUSER: t5459927; SAVECOUNT: 1; OriginalSymbolOrigin: (2540,7620); INSTANCENAME: cmp642; CDBNAME: C1210K
C60 = C: TIME: 17:22:43; UPDATEUSER: t5459927; SAVECOUNT: 1; OriginalSymbolOrigin: (2540,7620); INSTANCENAME: cmp627; CDBNAME: C1210K
CON4 CON5 = B2B_XH_A: as CON2 on sheet 1
D49 D50 = D: as D1 on sheet 1
L3 = L: COMP: CLF12577NI_D; TIME: 17:22:43; UPDATEUSER: t5459927; SAVECOUNT: 1; OriginalSymbolOrigin: (2540,5080); INSTANCENAME: cmp573; CDBNAME: CLF12577NI-D
L4 = L: COMP: CLF12577NI_D; TIME: 17:22:43; UPDATEUSER: t5459927; SAVECOUNT: 1; OriginalSymbolOrigin: (2540,5080); INSTANCENAME: cmp646; CDBNAME: CLF12577NI-D
Q22 = MFNM: TIME: 17:22:43; SAVECOUNT: 1; SAVEAREA0: -6986,-322,29385,23602; UPDATEUSER: t5459927; OriginalSymbolOrigin: (5080,20320); COMPONENTNAME: Q; INSTANCENAME: cmp648; CDBNAME: TSOP6F
Q32 = MFNM: TIME: 17:22:43; SAVECOUNT: 1; SAVEAREA0: -6986,-322,29385,23602; UPDATEUSER: t5459927; OriginalSymbolOrigin: (5080,20320); COMPONENTNAME: Q; INSTANCENAME: cmp571; CDBNAME: TSOP6F
Q76 Q77 = MFNKR1: as Q1 on sheet 1
R52 = R: TIME: 17:22:43; UPDATEUSER: t5459927; SAVECOUNT: 1; OriginalSymbolOrigin: (5080,5080); INSTANCENAME: cmp587; CDBNAME: R2512
R53 = R: TIME: 17:22:43; UPDATEUSER: t5459927; SAVECOUNT: 1; OriginalSymbolOrigin: (5080,5080); INSTANCENAME: cmp639; CDBNAME: R0603
R54 = R: TIME: 17:22:43; UPDATEUSER: t5459927; SAVECOUNT: 1; OriginalSymbolOrigin: (5080,5080); INSTANCENAME: cmp605; CDBNAME: R0603_7
R67 = R: TIME: 17:22:43; UPDATEUSER: t5459927; SAVECOUNT: 1; OriginalSymbolOrigin: (5080,5080); INSTANCENAME: cmp568; CDBNAME: R2512
R68 = R: TIME: 17:22:43; UPDATEUSER: t5459927; SAVECOUNT: 1; OriginalSymbolOrigin: (5080,5080); INSTANCENAME: cmp636; CDBNAME: R0603
R69 = R: TIME: 17:22:43; UPDATEUSER: t5459927; SAVECOUNT: 1; OriginalSymbolOrigin: (5080,5080); INSTANCENAME: cmp595; CDBNAME: R0603_7
R122 = R: TIME: 17:22:43; UPDATEUSER: t5459927; SAVECOUNT: 1; OriginalSymbolOrigin: (5080,5080); VAL2: 100mW; INSTANCENAME: cmp617; CDBNAME: R0603_2
R123 = R: TIME: 17:22:43; UPDATEUSER: t5459927; SAVECOUNT: 1; OriginalSymbolOrigin: (5080,5080); INSTANCENAME: cmp598; CDBNAME: R0603
R124 = R: TIME: 17:22:43; UPDATEUSER: t5459927; SAVECOUNT: 1; OriginalSymbolOrigin: (5080,5080); VAL2: 100mW; INSTANCENAME: cmp619; CDBNAME: R0603_2
R140 = R#1: TIME: 17:22:43; UPDATEUSER: t5459927; SAVECOUNT: 1; OriginalSymbolOrigin: (5080,5080); CaptureCellPackProp: R##1; VAL2: 100mW; INSTANCENAME: cmp630; CDBNAME: R0603_11
R141 = R: TIME: 17:22:43; UPDATEUSER: t5459927; SAVECOUNT: 1; OriginalSymbolOrigin: (5080,5080); VAL2: 100mW; INSTANCENAME: cmp599; CDBNAME: R0603_10
R142 = R: TIME: 17:22:43; UPDATEUSER: t5459927; SAVECOUNT: 1; OriginalSymbolOrigin: (5080,5080); VAL2: 100mW; INSTANCENAME: cmp580; CDBNAME: R0603_8
R143 = R: TIME: 17:22:43; UPDATEUSER: t5459927; SAVECOUNT: 1; OriginalSymbolOrigin: (5080,5080); VAL2: 100mW; INSTANCENAME: cmp590; CDBNAME: R0603_6
R144 = R: TIME: 17:22:43; UPDATEUSER: t5459927; SAVECOUNT: 1; OriginalSymbolOrigin: (5080,5080); VAL2: 100mW; INSTANCENAME: cmp616; CDBNAME: R0603_1
R145 = R: TIME: 17:22:43; UPDATEUSER: t5459927; SAVECOUNT: 1; OriginalSymbolOrigin: (5080,5080); VAL2: 125mW; INSTANCENAME: cmp614; CDBNAME: R0603_12
R146 = R: TIME: 17:22:43; UPDATEUSER: t5459927; SAVECOUNT: 1; OriginalSymbolOrigin: (5080,5080); INSTANCENAME: cmp631; CDBNAME: R2512
R147 = R: TIME: 17:22:43; UPDATEUSER: t5459927; SAVECOUNT: 1; OriginalSymbolOrigin: (5080,5080); VAL2: 100mW; INSTANCENAME: cmp608; CDBNAME: R0603_6
R148 = R: TIME: 17:22:43; UPDATEUSER: t5459927; SAVECOUNT: 1; OriginalSymbolOrigin: (5080,5080); VAL2: 63mW; INSTANCENAME: cmp625; CDBNAME: R0603_9
R149 = R#1: TIME: 17:22:43; UPDATEUSER: t5459927; SAVECOUNT: 1; OriginalSymbolOrigin: (5080,5080); CaptureCellPackProp: R##1; VAL2: 100mW; INSTANCENAME: cmp612; CDBNAME: R0603_11
R150 = R: TIME: 17:22:43; UPDATEUSER: t5459927; SAVECOUNT: 1; OriginalSymbolOrigin: (5080,5080); VAL2: 100mW; INSTANCENAME: cmp594; CDBNAME: R0603_10
R151 = R: TIME: 17:22:43; UPDATEUSER: t5459927; SAVECOUNT: 1; OriginalSymbolOrigin: (5080,5080); VAL2: 100mW; INSTANCENAME: cmp583; CDBNAME: R0603_8
R152 = R: TIME: 17:22:43; UPDATEUSER: t5459927; SAVECOUNT: 1; OriginalSymbolOrigin: (5080,5080); VAL2: 100mW; INSTANCENAME: cmp577; CDBNAME: R0603_6
R153 = R: TIME: 17:22:43; UPDATEUSER: t5459927; SAVECOUNT: 1; OriginalSymbolOrigin: (5080,5080); VAL2: 100mW; INSTANCENAME: cmp610; CDBNAME: R0603_1
R154 = R: TIME: 17:22:43; UPDATEUSER: t5459927; SAVECOUNT: 1; OriginalSymbolOrigin: (5080,5080); VAL2: 125mW; INSTANCENAME: cmp604; CDBNAME: R0603_12
R155 = R: TIME: 17:22:43; UPDATEUSER: t5459927; SAVECOUNT: 1; OriginalSymbolOrigin: (5080,5080); INSTANCENAME: cmp597; CDBNAME: R2512
R156 = R: TIME: 17:22:43; UPDATEUSER: t5459927; SAVECOUNT: 1; OriginalSymbolOrigin: (5080,5080); VAL2: 100mW; INSTANCENAME: cmp586; CDBNAME: R0603_6
R157 = R: TIME: 17:22:43; UPDATEUSER: t5459927; SAVECOUNT: 1; OriginalSymbolOrigin: (5080,5080); VAL2: 63mW; INSTANCENAME: cmp611; CDBNAME: R0603_9
R186 = R: TIME: 17:22:43; UPDATEUSER: t5459927; SAVECOUNT: 1; OriginalSymbolOrigin: (5080,5080); INSTANCENAME: cmp644; CDBNAME: R0603
SJ3 = SJ2W: SAVECOUNT: 1; COMP: SJ_2; SAVEAREA0: -15743,-4510,23437,11881; UPDATEUSER: t5459927; UPDATETIME: 17:22:42; OriginalSymbolOrigin: (2540,7620); COMPONENTNAME: SJ; INSTANCENAME: cmp613
SJ4 = SJ2W: SAVECOUNT: 1; COMP: SJ_2; SAVEAREA0: -15743,-4510,23437,11881; UPDATEUSER: t5459927; UPDATETIME: 17:22:42; OriginalSymbolOrigin: (2540,7620); COMPONENTNAME: SJ; INSTANCENAME: cmp566
U6 U7 = MAX16834: as U1 on sheet 1
U?#2 = WAKU_DEF100: as U?#1 on sheet 1
ZD57 = ZD: TIME: 17:22:43; SAVECOUNT: 1; SAVEAREA0: -4630,-153,17114,13055; UPDATEUSER: t5459927; OriginalSymbolOrigin: (5080,5080); INSTANCENAME: cmp582; CDBNAME: USC
ZD58 = ZD: TIME: 17:22:43; SAVECOUNT: 1; SAVEAREA0: -4630,-153,17114,13055; UPDATEUSER: t5459927; OriginalSymbolOrigin: (5080,5080); INSTANCENAME: cmp593; CDBNAME: USC

## Sheet 3.SchDoc
size 420 x 297 mm
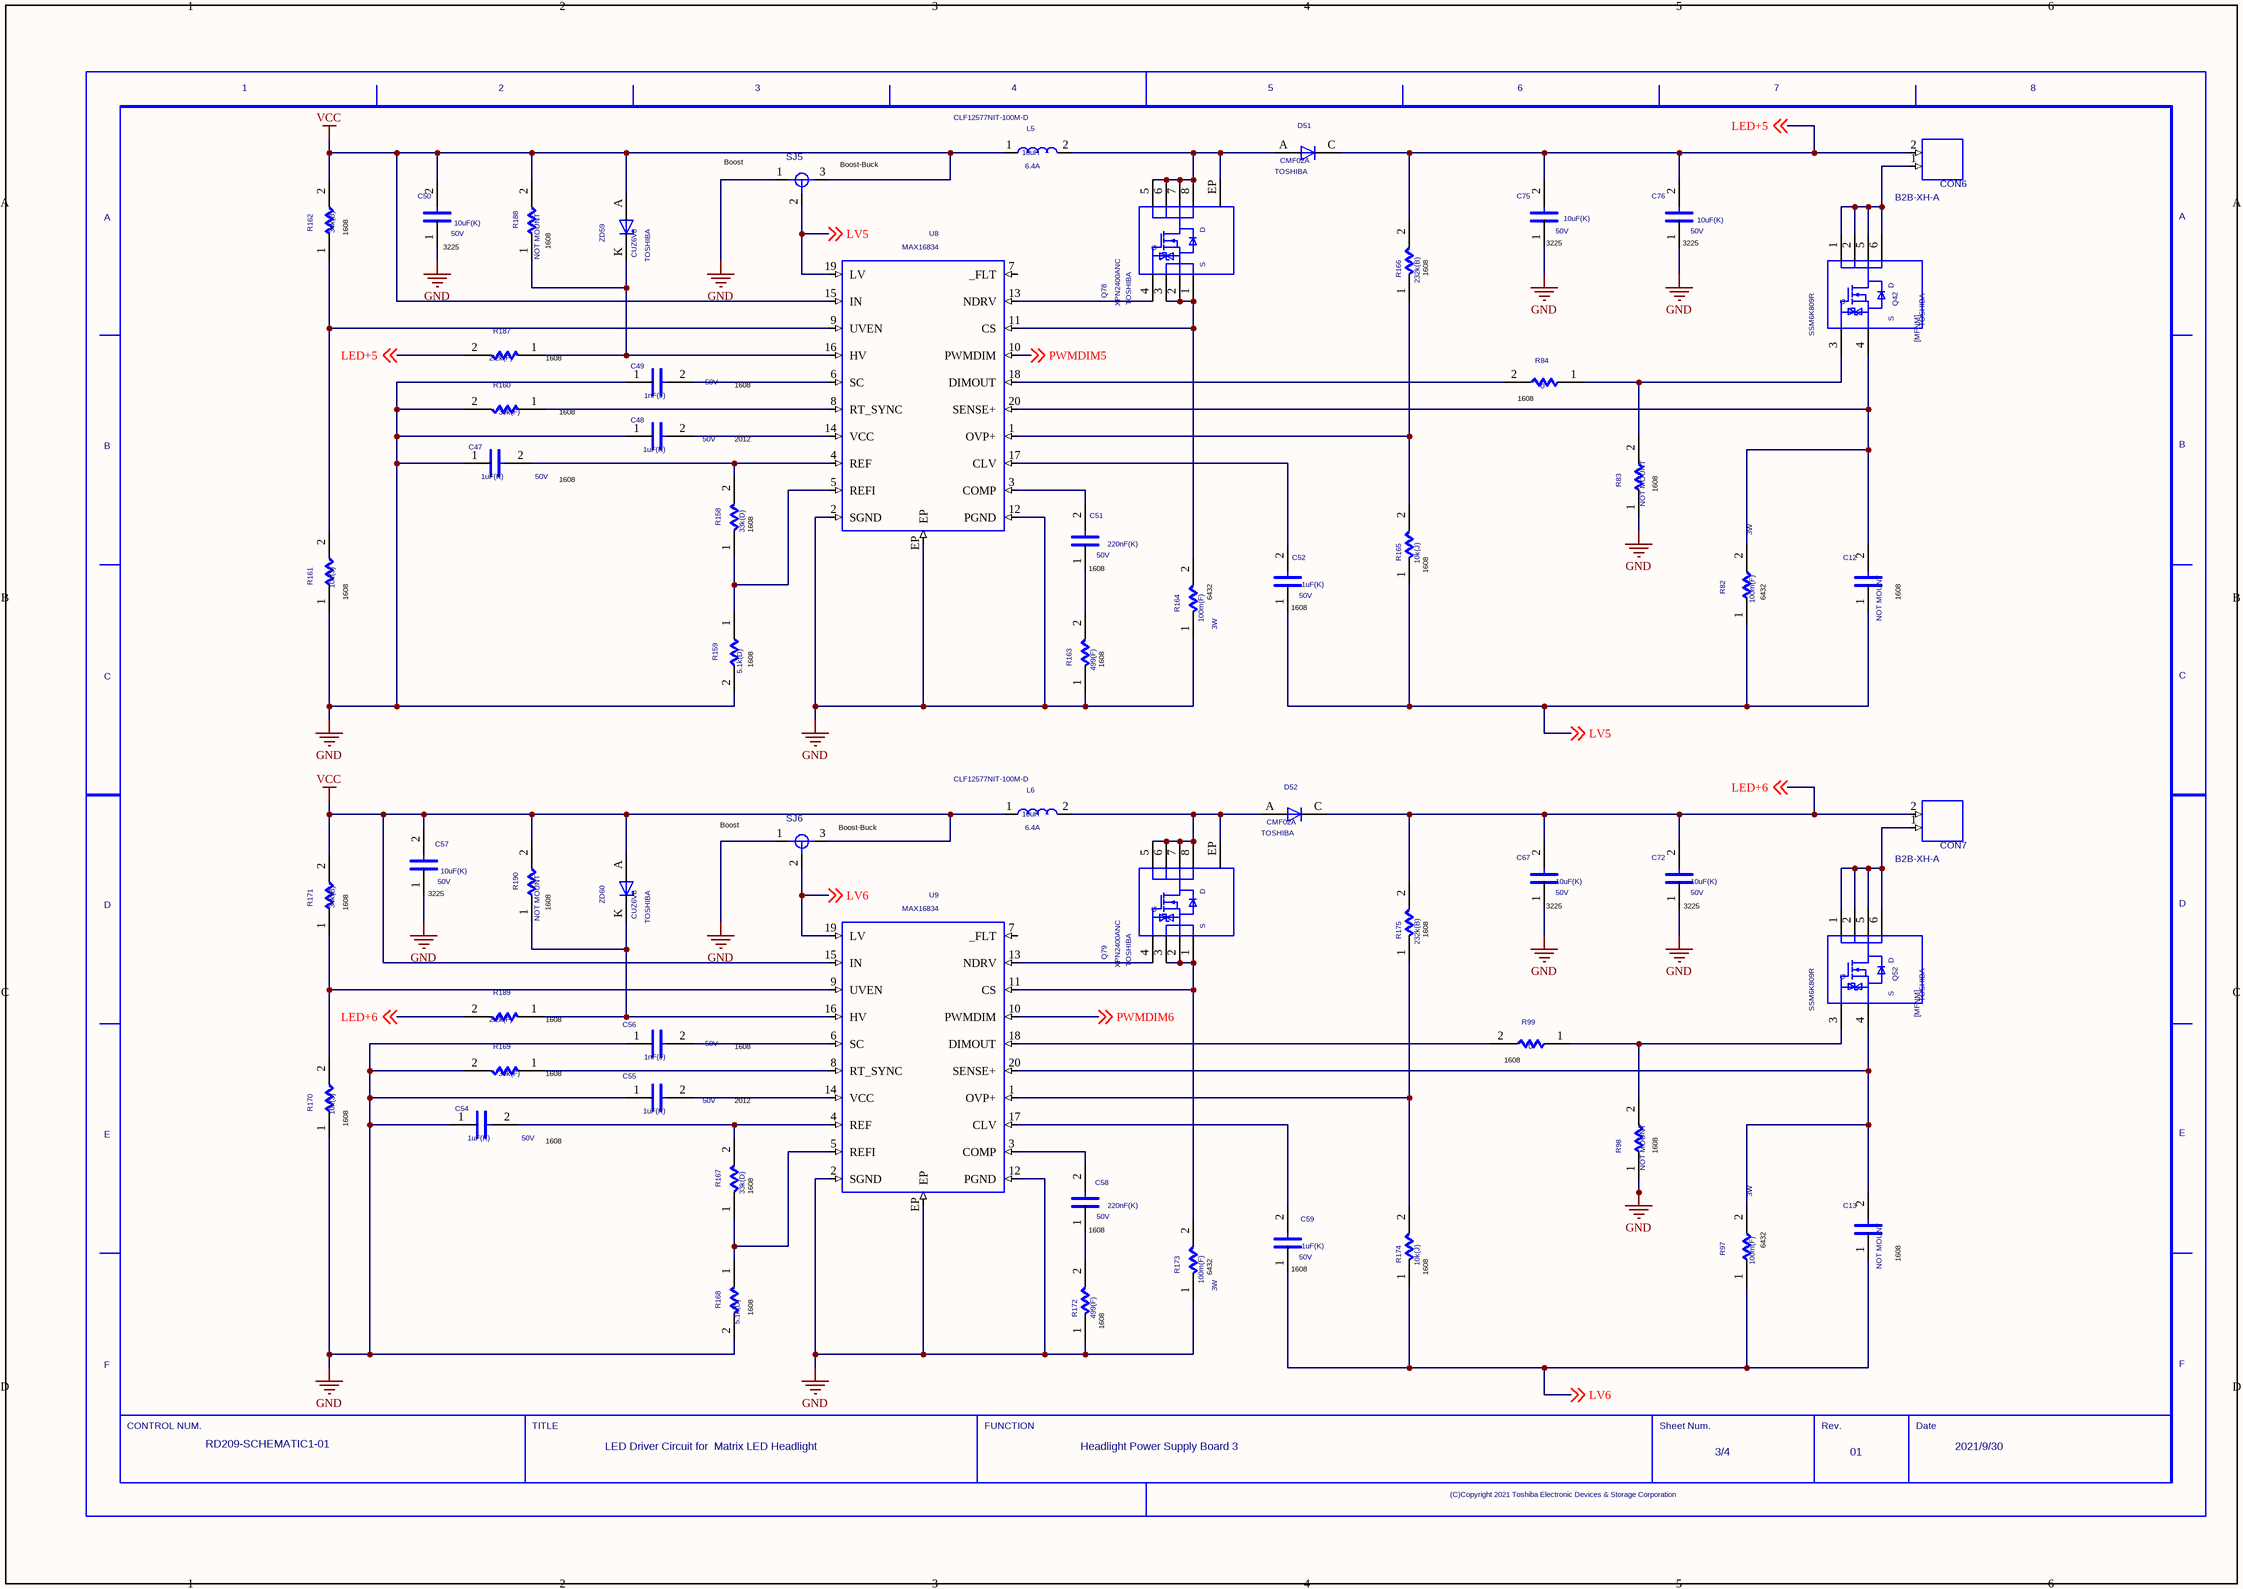
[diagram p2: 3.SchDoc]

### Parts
(Parts that share a designator on the sheet are numbered #1, #2 ... from top to bottom, then left to right.)
C12  NOTMOUNT: NOT MOUNT  (hidden comment: C)
C13  NOTMOUNT: NOT MOUNT  (hidden comment: C)
C47  VAL2: 50V  VAL1: 1uF(K)  (hidden comment: C)
C48  VAL2: 50V  VAL1: 1uF(K)  (hidden comment: C)
C49  VAL2: 50V  VAL1: 1nF(J)  (hidden comment: C)
C50  VAL2: 50V  VAL1: 10uF(K)  (hidden comment: C)
C51  VAL2: 50V  VAL1: 220nF(K)  (hidden comment: C)
C52  VAL2: 50V  VAL1: 1uF(K)  (hidden comment: C)
C54  VAL2: 50V  VAL1: 1uF(K)  (hidden comment: C)
C55  VAL2: 50V  VAL1: 1uF(K)  (hidden comment: C)
C56  VAL2: 50V  VAL1: 1nF(J)  (hidden comment: C)
C57  VAL2: 50V  VAL1: 10uF(K)  (hidden comment: C)
C58  VAL2: 50V  VAL1: 220nF(K)  (hidden comment: C)
C59  VAL2: 50V  VAL1: 1uF(K)  (hidden comment: C)
C67  VAL2: 50V  VAL1: 10uF(K)  (hidden comment: C)
C72  VAL2: 50V  VAL1: 10uF(K)  (hidden comment: C)
C75  VAL2: 50V  VAL1: 10uF(K)  (hidden comment: C)
C76  VAL2: 50V  VAL1: 10uF(K)  (hidden comment: C)
CON6  B2B-XH-A  [B2B-XH-A]
CON7  B2B-XH-A  [B2B-XH-A]
D51  USERCOMPTEXT3: TOSHIBA  VAL3: CMF02A  (hidden comment: D)
D52  USERCOMPTEXT3: TOSHIBA  VAL3: CMF02A  (hidden comment: D)
L5  VAL3: CLF12577NIT-100M-D  VAL2: 6.4A  VAL1: 10uH  (hidden comment: L)
L6  VAL3: CLF12577NIT-100M-D  VAL2: 6.4A  VAL1: 10uH  (hidden comment: L)
Q42  USERCOMPTEXT3: TOSHIBA  VAL3: SSM6K809R  (hidden comment: MFNM)
Q52  USERCOMPTEXT3: TOSHIBA  VAL3: SSM6K809R  (hidden comment: MFNM)
Q78  USERCOMPTEXT3: TOSHIBA  VAL3: XPN2400ANC  (hidden comment: MFNKR1)
Q79  USERCOMPTEXT3: TOSHIBA  VAL3: XPN2400ANC  (hidden comment: MFNKR1)
R82  VAL2: 3W  VAL1: 100m(F)  (hidden comment: R)
R83  NOTMOUNT: NOT MOUNT  (hidden comment: R)
R84  VAL1: 0  (hidden comment: R)
R97  VAL2: 3W  VAL1: 100m(F)  (hidden comment: R)
R98  NOTMOUNT: NOT MOUNT  (hidden comment: R)
R99  VAL1: 0  (hidden comment: R)
R158  VAL1: 33k(D)  (hidden comment: R)
R159  VAL1: 5.1k(D)  (hidden comment: R)
R160  VAL1: 39k(F)  (hidden comment: R)
R161  VAL1: 10k(J)  (hidden comment: R)
R162  VAL1: 34k(B)  (hidden comment: R)
R163  VAL1: 499(F)  (hidden comment: R)
R164  VAL2: 3W  VAL1: 100m(F)  (hidden comment: R)
R165  VAL1: 10k(J)  (hidden comment: R)
R166  VAL1: 232k(B)  (hidden comment: R)
R167  VAL1: 33k(D)  (hidden comment: R)
R168  VAL1: 5.1k(D)  (hidden comment: R)
R169  VAL1: 39k(F)  (hidden comment: R)
R170  VAL1: 10k(J)  (hidden comment: R)
R171  VAL1: 34k(B)  (hidden comment: R)
R172  VAL1: 499(F)  (hidden comment: R)
R173  VAL2: 3W  VAL1: 100m(F)  (hidden comment: R)
R174  VAL1: 10k(J)  (hidden comment: R)
R175  VAL1: 232k(B)  (hidden comment: R)
R187  VAL1: 2.2k(F)  (hidden comment: R)
R188  NOTMOUNT: NOT MOUNT  (hidden comment: R)
R189  VAL1: 2.2k(F)  (hidden comment: R)
R190  NOTMOUNT: NOT MOUNT  (hidden comment: R)
SJ5  SJ2W  (value not drawn)
SJ6  SJ2W  (value not drawn)
U8  MAX16834
U9  MAX16834
U?#3  DATE: 2021/9/30  REVISION: 01  DRAWINGNUMBER: RD209-SCHEMATIC1-01  FUNCTION: Headlight Power Supply Board 3  SHEETNUMBER: 3/4  TITLE: LED Driver Circuit for / Matrix LED Headlight  (hidden comment: WAKU_DEF100)
ZD59  USERCOMPTEXT3: TOSHIBA  VAL3: CUZ6V8  (hidden comment: ZD)
ZD60  USERCOMPTEXT3: TOSHIBA  VAL3: CUZ6V8  (hidden comment: ZD)

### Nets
GND: C47.1 C48.1 C49.1 C50.1 C54.1 C55.1 C56.1 C57.1 C67.1 C72.1 C75.1 C76.1 R83.1 R98.1 R159.2 R160.2 R161.1 R163.1 R164.1 R168.2 R169.2 R170.1 R172.1 R173.1 SJ5.1 SJ6.1 U8.2(SGND) U8.12(PGND) U8.EP U9.2(SGND) U9.12(PGND) U9.EP
VCC: C50.2 C57.2 L5.1 L6.1 R162.2 R171.2 R188.2 R190.2 SJ5.3 SJ6.3 U8.15(IN) U9.15(IN) ZD59.A ZD60.A
LED+5: C75.2 C76.2 CON6.2 D51.C R166.2 R187.2 ; off-sheet LED+5
LED+6: C67.2 C72.2 CON7.2 D52.C R175.2 R189.2 ; off-sheet LED+6
LV5: C12.1 C52.1 R82.1 R165.1 SJ5.2 U8.19(LV) ; off-sheet LV5
LV6: C13.1 C59.1 R97.1 R174.1 SJ6.2 U9.19(LV) ; off-sheet LV6
PWMDIM5: U8.10(PWMDIM) ; off-sheet PWMDIM5
PWMDIM6: U9.10(PWMDIM) ; off-sheet PWMDIM6
SIG719: C59.2 U9.17(CLV)
SIG721: R160.1 U8.8(RT_SYNC)
SIG722: C58.2 U9.3(COMP)
SIG723: Q79.1 Q79.2 Q79.3 R173.2 U9.11(CS)
SIG724: D52.A L6.2 Q79.5 Q79.6 Q79.7 Q79.8 Q79.EP
SIG727: CON7.1 Q52.1 Q52.2 Q52.5 Q52.6
SIG729: C48.2 U8.14(VCC)
SIG730: Q78.4 U8.13(NDRV)
SIG732: R158.1 R159.1 U8.5(REFI)
SIG733: C49.2 U8.6(SC)
SIG735: C51.2 U8.3(COMP)
SIG736: C52.2 U8.17(CLV)
SIG737: C47.2 R158.2 U8.4(REF)
SIG738: C13.2 Q52.4 R97.2 U9.20(SENSE+)
SIG740: Q78.1 Q78.2 Q78.3 R164.2 U8.11(CS)
SIG741: R187.1 R188.1 U8.16(HV) ZD59.K(C)
SIG743: CON6.1 Q42.1 Q42.2 Q42.5 Q42.6
SIG744: Q42.3 R83.2 R84.1
SIG745: C51.1 R163.2
SIG746: C58.1 R172.2
SIG748: R170.2 R171.1 U9.9(UVEN)
SIG749: Q79.4 U9.13(NDRV)
SIG750: C54.2 R167.2 U9.4(REF)
SIG753: C55.2 U9.14(VCC)
SIG754: C12.2 Q42.4 R82.2 U8.20(SENSE+)
SIG755: D51.A L5.2 Q78.5 Q78.6 Q78.7 Q78.8 Q78.EP
SIG756: R167.1 R168.1 U9.5(REFI)
SIG760: R189.1 R190.1 U9.16(HV) ZD60.K(C)
SIG761: R84.2 U8.18(DIMOUT)
SIG763: R174.2 R175.1 U9.1(OVP+)
SIG764: R165.2 R166.1 U8.1(OVP+)
SIG765: C56.2 U9.6(SC)
SIG766: R99.2 U9.18(DIMOUT)
SIG767: R169.1 U9.8(RT_SYNC)
SIG768: R161.2 R162.1 U8.9(UVEN)
SIG770: Q52.3 R98.2 R99.1

Not connected (* = marked no-connect by the designer): U8 7(_FLT); U9 7(_FLT)

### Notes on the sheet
- (near SJ5) Boost
- (near SJ5) Boost-Buck
- (near R162) 1608
- (near C50) 3225
- (near R188) 1608
- (near C75) 3225
- (near C76) 3225
- (near R166) 1608
- (near R187) 1608
- 1608
- (near R160) 1608
- 2012
- (near R84) 1608
- (near R158) 1608
- (near R83) 1608
- (near R161) 1608
- (near C51) 1608
- (near R164) 6432
- (near R165) 1608
- (near R82) 6432
- (near C12) 1608
- (near R159) 1608
- (near R163) 1608
- (near C52) 1608
- (near SJ6) Boost
- (near SJ6) Boost-Buck
- (near R171) 1608
- (near C57) 3225
- (near R190) 1608
- (near R175) 1608
- (near C67) 3225
- (near C72) 3225
- (near R189) 1608
- (near R99) 1608
- (near R170) 1608
- (near R169) 1608
- (near R167) 1608
- (near R98) 1608
- (near C58) 1608
- (near R173) 6432
- (near C59) 1608
- (near R174) 1608
- (near R97) 6432
- (near C13) 1608
- (near R168) 1608
- (near R172) 1608

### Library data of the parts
C12 = C: TIME: 17:22:43; UPDATEUSER: t5459927; SAVECOUNT: 1; OriginalSymbolOrigin: (2540,7620); INSTANCENAME: cmp123; CDBNAME: C0603K
C13 = C: TIME: 17:22:43; UPDATEUSER: t5459927; SAVECOUNT: 1; OriginalSymbolOrigin: (2540,7620); INSTANCENAME: cmp180; CDBNAME: C0603K
C47 = C: TIME: 17:22:43; UPDATEUSER: t5459927; SAVECOUNT: 1; OriginalSymbolOrigin: (2540,7620); INSTANCENAME: cmp124; CDBNAME: C0603K_3
C48 = C: TIME: 17:22:43; UPDATEUSER: t5459927; SAVECOUNT: 1; OriginalSymbolOrigin: (2540,7620); INSTANCENAME: cmp113; CDBNAME: C0805K_1
C49 = C: TIME: 17:22:43; UPDATEUSER: t5459927; SAVECOUNT: 1; OriginalSymbolOrigin: (2540,7620); INSTANCENAME: cmp171; CDBNAME: C0603K_1
C50 = C: TIME: 17:22:43; UPDATEUSER: t5459927; SAVECOUNT: 1; OriginalSymbolOrigin: (2540,7620); INSTANCENAME: cmp149; CDBNAME: C1210K
C51 = C: TIME: 17:22:43; UPDATEUSER: t5459927; SAVECOUNT: 1; OriginalSymbolOrigin: (2540,7620); INSTANCENAME: cmp114; CDBNAME: C0603K_4
C52 = C: TIME: 17:22:43; UPDATEUSER: t5459927; SAVECOUNT: 1; OriginalSymbolOrigin: (2540,7620); INSTANCENAME: cmp167; CDBNAME: C0603K_3
C54 = C: TIME: 17:22:43; UPDATEUSER: t5459927; SAVECOUNT: 1; OriginalSymbolOrigin: (2540,7620); INSTANCENAME: cmp144; CDBNAME: C0603K_3
C55 = C: TIME: 17:22:43; UPDATEUSER: t5459927; SAVECOUNT: 1; OriginalSymbolOrigin: (2540,7620); INSTANCENAME: cmp147; CDBNAME: C0805K_1
C56 = C: TIME: 17:22:43; UPDATEUSER: t5459927; SAVECOUNT: 1; OriginalSymbolOrigin: (2540,7620); INSTANCENAME: cmp153; CDBNAME: C0603K_1
C57 = C: TIME: 17:22:43; UPDATEUSER: t5459927; SAVECOUNT: 1; OriginalSymbolOrigin: (2540,7620); INSTANCENAME: cmp166; CDBNAME: C1210K
C58 = C: TIME: 17:22:43; UPDATEUSER: t5459927; SAVECOUNT: 1; OriginalSymbolOrigin: (2540,7620); INSTANCENAME: cmp119; CDBNAME: C0603K_4
C59 = C: TIME: 17:22:43; UPDATEUSER: t5459927; SAVECOUNT: 1; OriginalSymbolOrigin: (2540,7620); INSTANCENAME: cmp148; CDBNAME: C0603K_3
C67 = C: TIME: 17:22:43; UPDATEUSER: t5459927; SAVECOUNT: 1; OriginalSymbolOrigin: (2540,7620); INSTANCENAME: cmp111; CDBNAME: C1210K
C72 = C: TIME: 17:22:43; UPDATEUSER: t5459927; SAVECOUNT: 1; OriginalSymbolOrigin: (2540,7620); INSTANCENAME: cmp175; CDBNAME: C1210K
C75 = C: TIME: 17:22:43; UPDATEUSER: t5459927; SAVECOUNT: 1; OriginalSymbolOrigin: (2540,7620); INSTANCENAME: cmp157; CDBNAME: C1210K
C76 = C: TIME: 17:22:43; UPDATEUSER: t5459927; SAVECOUNT: 1; OriginalSymbolOrigin: (2540,7620); INSTANCENAME: cmp173; CDBNAME: C1210K
CON6 CON7 = B2B_XH_A: as CON2 on sheet 1
D51 D52 = D: as D1 on sheet 1
L5 = L: COMP: CLF12577NI_D; TIME: 17:22:43; UPDATEUSER: t5459927; SAVECOUNT: 1; OriginalSymbolOrigin: (2540,5080); INSTANCENAME: cmp146; CDBNAME: CLF12577NI-D
L6 = L: COMP: CLF12577NI_D; TIME: 17:22:43; UPDATEUSER: t5459927; SAVECOUNT: 1; OriginalSymbolOrigin: (2540,5080); INSTANCENAME: cmp190; CDBNAME: CLF12577NI-D
Q42 = MFNM: TIME: 17:22:43; SAVECOUNT: 1; SAVEAREA0: -6986,-322,29385,23602; UPDATEUSER: t5459927; OriginalSymbolOrigin: (5080,20320); COMPONENTNAME: Q; INSTANCENAME: cmp117; CDBNAME: TSOP6F
Q52 = MFNM: TIME: 17:22:43; SAVECOUNT: 1; SAVEAREA0: -6986,-322,29385,23602; UPDATEUSER: t5459927; OriginalSymbolOrigin: (5080,20320); COMPONENTNAME: Q; INSTANCENAME: cmp187; CDBNAME: TSOP6F
Q78 Q79 = MFNKR1: as Q1 on sheet 1
R82 = R: TIME: 17:22:43; UPDATEUSER: t5459927; SAVECOUNT: 1; OriginalSymbolOrigin: (5080,5080); INSTANCENAME: cmp162; CDBNAME: R2512
R83 = R: TIME: 17:22:43; UPDATEUSER: t5459927; SAVECOUNT: 1; OriginalSymbolOrigin: (5080,5080); INSTANCENAME: cmp181; CDBNAME: R0603
R84 = R: TIME: 17:22:43; UPDATEUSER: t5459927; SAVECOUNT: 1; OriginalSymbolOrigin: (5080,5080); INSTANCENAME: cmp128; CDBNAME: R0603_7
R97 = R: TIME: 17:22:43; UPDATEUSER: t5459927; SAVECOUNT: 1; OriginalSymbolOrigin: (5080,5080); INSTANCENAME: cmp169; CDBNAME: R2512
R98 = R: TIME: 17:22:43; UPDATEUSER: t5459927; SAVECOUNT: 1; OriginalSymbolOrigin: (5080,5080); INSTANCENAME: cmp125; CDBNAME: R0603
R99 = R: TIME: 17:22:43; UPDATEUSER: t5459927; SAVECOUNT: 1; OriginalSymbolOrigin: (5080,5080); INSTANCENAME: cmp191; CDBNAME: R0603_7
R158 = R#1: TIME: 17:22:43; UPDATEUSER: t5459927; SAVECOUNT: 1; OriginalSymbolOrigin: (5080,5080); CaptureCellPackProp: R##1; VAL2: 100mW; INSTANCENAME: cmp155; CDBNAME: R0603_11
R159 = R: TIME: 17:22:43; UPDATEUSER: t5459927; SAVECOUNT: 1; OriginalSymbolOrigin: (5080,5080); VAL2: 100mW; INSTANCENAME: cmp145; CDBNAME: R0603_10
R160 = R: TIME: 17:22:43; UPDATEUSER: t5459927; SAVECOUNT: 1; OriginalSymbolOrigin: (5080,5080); VAL2: 100mW; INSTANCENAME: cmp163; CDBNAME: R0603_8
R161 = R: TIME: 17:22:43; UPDATEUSER: t5459927; SAVECOUNT: 1; OriginalSymbolOrigin: (5080,5080); VAL2: 100mW; INSTANCENAME: cmp122; CDBNAME: R0603_6
R162 = R: TIME: 17:22:43; UPDATEUSER: t5459927; SAVECOUNT: 1; OriginalSymbolOrigin: (5080,5080); VAL2: 100mW; INSTANCENAME: cmp136; CDBNAME: R0603_1
R163 = R: TIME: 17:22:43; UPDATEUSER: t5459927; SAVECOUNT: 1; OriginalSymbolOrigin: (5080,5080); VAL2: 125mW; INSTANCENAME: cmp135; CDBNAME: R0603_12
R164 = R: TIME: 17:22:43; UPDATEUSER: t5459927; SAVECOUNT: 1; OriginalSymbolOrigin: (5080,5080); INSTANCENAME: cmp164; CDBNAME: R2512
R165 = R: TIME: 17:22:43; UPDATEUSER: t5459927; SAVECOUNT: 1; OriginalSymbolOrigin: (5080,5080); VAL2: 100mW; INSTANCENAME: cmp139; CDBNAME: R0603_6
R166 = R: TIME: 17:22:43; UPDATEUSER: t5459927; SAVECOUNT: 1; OriginalSymbolOrigin: (5080,5080); VAL2: 63mW; INSTANCENAME: cmp168; CDBNAME: R0603_9
R167 = R#1: TIME: 17:22:43; UPDATEUSER: t5459927; SAVECOUNT: 1; OriginalSymbolOrigin: (5080,5080); CaptureCellPackProp: R##1; VAL2: 100mW; INSTANCENAME: cmp158; CDBNAME: R0603_11
R168 = R: TIME: 17:22:43; UPDATEUSER: t5459927; SAVECOUNT: 1; OriginalSymbolOrigin: (5080,5080); VAL2: 100mW; INSTANCENAME: cmp179; CDBNAME: R0603_10
R169 = R: TIME: 17:22:43; UPDATEUSER: t5459927; SAVECOUNT: 1; OriginalSymbolOrigin: (5080,5080); VAL2: 100mW; INSTANCENAME: cmp127; CDBNAME: R0603_8
R170 = R: TIME: 17:22:43; UPDATEUSER: t5459927; SAVECOUNT: 1; OriginalSymbolOrigin: (5080,5080); VAL2: 100mW; INSTANCENAME: cmp131; CDBNAME: R0603_6
R171 = R: TIME: 17:22:43; UPDATEUSER: t5459927; SAVECOUNT: 1; OriginalSymbolOrigin: (5080,5080); VAL2: 100mW; INSTANCENAME: cmp116; CDBNAME: R0603_1
R172 = R: TIME: 17:22:43; UPDATEUSER: t5459927; SAVECOUNT: 1; OriginalSymbolOrigin: (5080,5080); VAL2: 125mW; INSTANCENAME: cmp176; CDBNAME: R0603_12
R173 = R: TIME: 17:22:43; UPDATEUSER: t5459927; SAVECOUNT: 1; OriginalSymbolOrigin: (5080,5080); INSTANCENAME: cmp115; CDBNAME: R2512
R174 = R: TIME: 17:22:43; UPDATEUSER: t5459927; SAVECOUNT: 1; OriginalSymbolOrigin: (5080,5080); VAL2: 100mW; INSTANCENAME: cmp134; CDBNAME: R0603_6
R175 = R: TIME: 17:22:43; UPDATEUSER: t5459927; SAVECOUNT: 1; OriginalSymbolOrigin: (5080,5080); VAL2: 63mW; INSTANCENAME: cmp185; CDBNAME: R0603_9
R187 = R: TIME: 17:22:43; UPDATEUSER: t5459927; SAVECOUNT: 1; OriginalSymbolOrigin: (5080,5080); VAL2: 100mW; INSTANCENAME: cmp109; CDBNAME: R0603_2
R188 = R: TIME: 17:22:43; UPDATEUSER: t5459927; SAVECOUNT: 1; OriginalSymbolOrigin: (5080,5080); INSTANCENAME: cmp137; CDBNAME: R0603
R189 = R: TIME: 17:22:43; UPDATEUSER: t5459927; SAVECOUNT: 1; OriginalSymbolOrigin: (5080,5080); VAL2: 100mW; INSTANCENAME: cmp189; CDBNAME: R0603_2
R190 = R: TIME: 17:22:43; UPDATEUSER: t5459927; SAVECOUNT: 1; OriginalSymbolOrigin: (5080,5080); INSTANCENAME: cmp156; CDBNAME: R0603
SJ5 = SJ2W: SAVECOUNT: 1; COMP: SJ_2; SAVEAREA0: -15743,-4510,23437,11881; UPDATEUSER: t5459927; UPDATETIME: 17:22:42; OriginalSymbolOrigin: (2540,7620); COMPONENTNAME: SJ; INSTANCENAME: cmp132
SJ6 = SJ2W: SAVECOUNT: 1; COMP: SJ_2; SAVEAREA0: -15743,-4510,23437,11881; UPDATEUSER: t5459927; UPDATETIME: 17:22:42; OriginalSymbolOrigin: (2540,7620); COMPONENTNAME: SJ; INSTANCENAME: cmp196
U8 U9 = MAX16834: as U1 on sheet 1
U?#3 = WAKU_DEF100: as U?#1 on sheet 1
ZD59 = ZD: TIME: 17:22:43; SAVECOUNT: 1; SAVEAREA0: -4630,-153,17114,13055; UPDATEUSER: t5459927; OriginalSymbolOrigin: (5080,5080); INSTANCENAME: cmp183; CDBNAME: USC
ZD60 = ZD: TIME: 17:22:43; SAVECOUNT: 1; SAVEAREA0: -4630,-153,17114,13055; UPDATEUSER: t5459927; OriginalSymbolOrigin: (5080,5080); INSTANCENAME: cmp192; CDBNAME: USC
